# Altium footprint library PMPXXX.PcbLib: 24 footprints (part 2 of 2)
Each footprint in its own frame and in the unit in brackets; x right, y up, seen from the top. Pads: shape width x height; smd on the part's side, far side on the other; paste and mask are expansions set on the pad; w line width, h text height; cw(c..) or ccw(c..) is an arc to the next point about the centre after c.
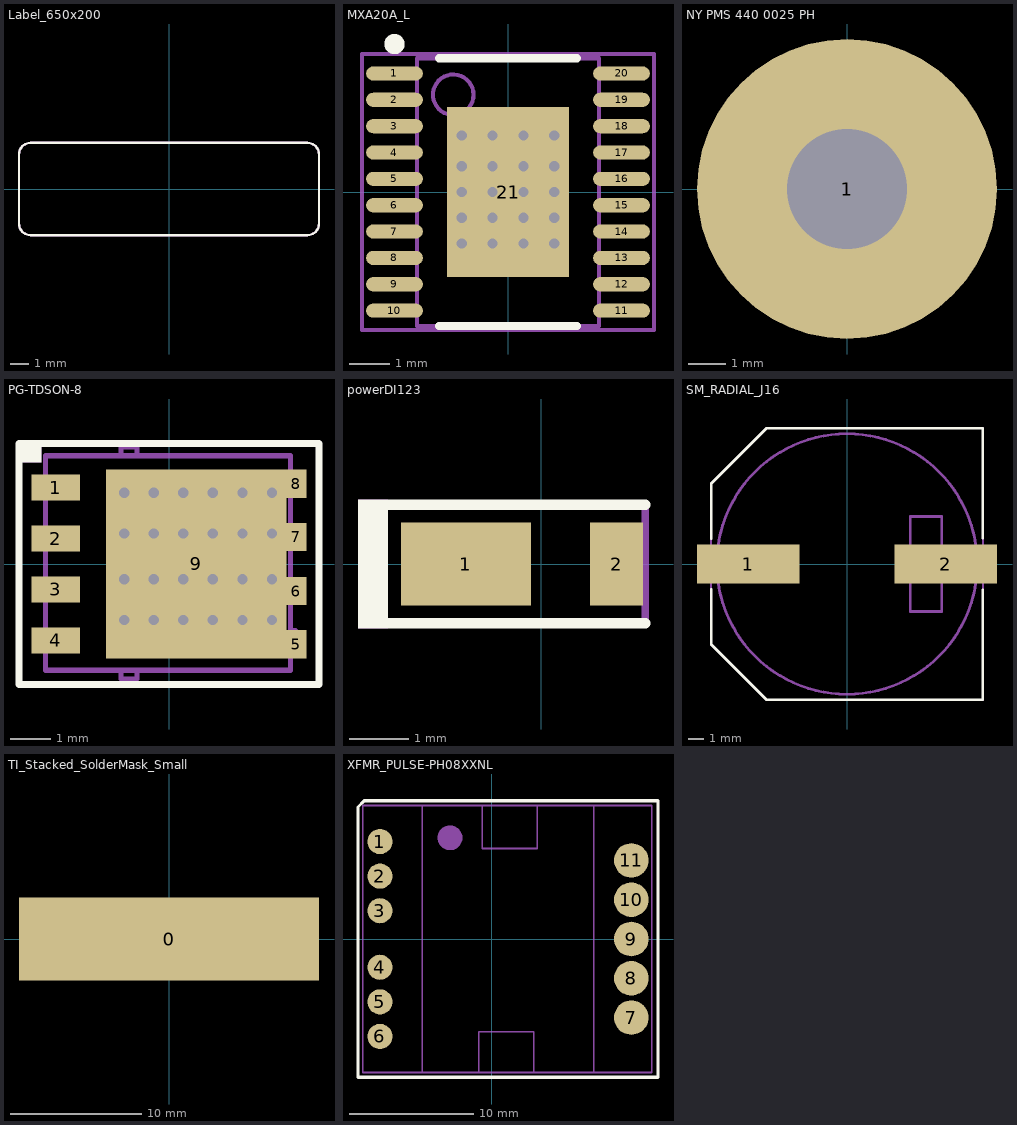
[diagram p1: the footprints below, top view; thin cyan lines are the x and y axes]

## Label_650x200 [mm] "Thermal Transfer Label"
height 0.025
Top Overlay:
  lines w0.127: -8.255,-1.905 ccw(c-7.62,-1.905) -7.62,-2.54 7.62,-2.54 ccw(c7.62,-1.905) 8.255,-1.905 8.255,1.905 ccw(c7.62,1.905) 7.62,2.54 -7.62,2.54 ccw(c-7.62,1.905) -8.255,1.905 -8.255,-1.905
Mechanical 5:
  lines w0.127: -8.255,-1.905 ccw(c-7.62,-1.905) -7.62,-2.54 7.62,-2.54 ccw(c7.62,-1.905) 8.255,-1.905 8.255,1.905 ccw(c7.62,1.905) 7.62,2.54 -7.62,2.54 ccw(c-7.62,1.905) -8.255,1.905 -8.255,-1.905
  text ".Designator" at -1.524,-0.508 h1.02
3D body: height 0.03, standoff 0, extent -8.268,-2.553 8.268,2.553

## MXA20A_L [mm] "TSOP, 20-Leads, Body 6.5x4.4mm, Pitch 0.65mm, Exposed Pad, IPC High Density"
height 1.1
pads (21):
  oval 1.4x0.35 smd: 1(-2.8,2.925) 2(-2.8,2.275) 3(-2.8,1.625) 4(-2.8,0.975) 5(-2.8,0.325) 6(-2.8,-0.325) 7(-2.8,-0.975) 8(-2.8,-1.625) 9(-2.8,-2.275) 10(-2.8,-2.925) 11(2.8,-2.925) 12(2.8,-2.275) 13(2.8,-1.625) 14(2.8,-0.975) 15(2.8,-0.325) 16(2.8,0.325) 17(2.8,0.975) 18(2.8,1.625) 19(2.8,2.275) 20(2.8,2.925)
  rect 3x4.2 smd: 21(0,0)
via 1.143,1.397 diameter 0.508 hole 0.254
via 0.381,1.397 diameter 0.508 hole 0.254
via -1.143,1.397 diameter 0.508 hole 0.254
via -0.381,1.397 diameter 0.508 hole 0.254
via -0.381,0.635 diameter 0.508 hole 0.254
via -1.143,0.635 diameter 0.508 hole 0.254
via 0.381,0.635 diameter 0.508 hole 0.254
via 1.143,0.635 diameter 0.508 hole 0.254
via -1.143,0 diameter 0.508 hole 0.254
via 0.381,0 diameter 0.508 hole 0.254
via 1.143,0 diameter 0.508 hole 0.254
via -0.381,-0.635 diameter 0.508 hole 0.254
via -1.143,-0.635 diameter 0.508 hole 0.254
via 0.381,-0.635 diameter 0.508 hole 0.254
via 1.143,-0.635 diameter 0.508 hole 0.254
via -0.381,-1.27 diameter 0.508 hole 0.254
via -1.143,-1.27 diameter 0.508 hole 0.254
via 0.381,-1.27 diameter 0.508 hole 0.254
via 1.143,-1.27 diameter 0.508 hole 0.254
via -0.381,0 diameter 0.508 hole 0.254
Top Overlay:
  circle w0.25: c-2.8,3.65 r0.125
  lines w0.2: -1.7,-3.3 1.7,-3.3 ; -1.7,3.3 1.7,3.3
Mechanical 5:
  circle w0.1: c-1.35,2.4 r0.5
  lines w0.1: -2.25,-3.3 2.25,-3.3 2.25,3.3 -2.25,3.3 -2.25,-3.3
  text ".Designator" at -1.524,-0.508 h1.02
Mechanical 15:
  lines w0.1: -0.5,0 0.5,0 ; 0,-0.5 0,0.5 ; -3.6,-3.4 3.6,-3.4 3.6,3.4 -3.6,3.4 -3.6,-3.4
3D body: height 1.1, standoff 0, extent -2.25,-3.3 2.25,3.3

## NY PMS 440 0025 PH [mm] "4-40 nylon screw and mounting hole"
height 1.905
pads (1):
  round 8 hole 3.2: 1(0,0)
Mechanical 5:
  circle w0.127: c0,0 r3.789
  text ".Designator" at -1.524,-0.508 h1.02
3D body: height 2.69, standoff -8.74, extent -3.302,-3.3 3.296,3.3

## PG-TDSON-8 [mm] "Infineon recommended land pattern"
height 1.1
pads (9):
  rect 1.2x0.65 smd: 1(-2.825,1.905) 2(-2.825,0.635) 3(-2.825,-0.635) 4(-2.825,-1.905)
  rect 0.5x0.7 smd: 5(3.175,-2) 6(3.175,-0.675) 7(3.175,0.675) 8(3.175,2)
  rect 4.5x4.7 smd paste-2.25: 9(0.675,0)
via 2.565,-1.397 diameter 0.508 hole 0.254
via 1.829,-1.397 diameter 0.508 hole 0.254
via 1.092,-1.397 diameter 0.508 hole 0.254
via 0.356,-1.397 diameter 0.508 hole 0.254
via -0.381,-1.397 diameter 0.508 hole 0.254
via -1.118,-1.397 diameter 0.508 hole 0.254
via -1.118,-0.381 diameter 0.508 hole 0.254
via -0.381,-0.381 diameter 0.508 hole 0.254
via 0.356,-0.381 diameter 0.508 hole 0.254
via 1.092,-0.381 diameter 0.508 hole 0.254
via 1.829,-0.381 diameter 0.508 hole 0.254
via 2.565,-0.381 diameter 0.508 hole 0.254
via 2.565,1.778 diameter 0.508 hole 0.254
via 1.829,1.778 diameter 0.508 hole 0.254
via 1.092,1.778 diameter 0.508 hole 0.254
via 0.356,1.778 diameter 0.508 hole 0.254
via -0.381,1.778 diameter 0.508 hole 0.254
via -1.118,1.778 diameter 0.508 hole 0.254
via -1.118,0.762 diameter 0.508 hole 0.254
via -0.381,0.762 diameter 0.508 hole 0.254
via 0.356,0.762 diameter 0.508 hole 0.254
via 1.092,0.762 diameter 0.508 hole 0.254
via 1.829,0.762 diameter 0.508 hole 0.254
via 2.565,0.762 diameter 0.508 hole 0.254
Top Overlay:
  rectangle: -3.74,2.528 -3.175,2.975
  lines w0.178: -3.74,-3 -3.74,0 -3.74,3 0.105,3 3.74,3 3.74,0 3.74,-3 -0.105,-3 -3.74,-3
Top Paste:
  rectangle: -1.475,0.95 -0.242,2.25
  rectangle: 0.058,0.95 1.291,2.25
  rectangle: 1.591,0.95 2.824,2.25
  rectangle: -1.475,-0.65 -0.242,0.65
  rectangle: 0.058,-0.65 1.291,0.65
  rectangle: 1.591,-0.65 2.824,0.65
  rectangle: 1.591,-2.25 2.824,-0.95
  rectangle: 0.058,-2.25 1.291,-0.95
  rectangle: -1.475,-2.25 -0.242,-0.95
Mechanical 5:
  rectangle: -3.74,2.528 -3.175,2.975
  lines w0.127: -3.075,-2.1 -3.2,-2.1 -3.2,-1.66 -3.075,-1.66 ; -3.075,-0.83 -3.2,-0.83 -3.2,-0.39 -3.075,-0.39 ; -3.075,0.44 -3.2,0.44 -3.2,0.88 -3.075,0.88 ; -3.075,1.71 -3.2,1.71 -3.2,2.15 -3.075,2.15 ; -1.2,-2.65 -1.2,-2.87 -0.8,-2.87 -0.8,-2.65 ; -1.2,2.7 -1.2,2.92 -0.8,2.92 -0.8,2.7 ; 3.025,-2.1 3.15,-2.1 3.15,-1.66 3.025,-1.66 ; 3.025,-0.83 3.15,-0.83 3.15,-0.39 3.025,-0.39 ; 3.025,0.44 3.15,0.44 3.15,0.88 3.025,0.88 ; 3.025,1.71 3.15,1.71 3.15,2.15 3.025,2.15 ; -3.075,-2.65 3.025,-2.65 3.025,2.7 -3.075,2.7 -3.075,-2.65
  text ".Designator" at -1.925,-0.5 h1.02
3D body: height 1.1, standoff 0, extent 1.778,-6.679 8.128,-0.889

## powerDI123 [mm] "Diodes Inc recommended land pattern, document number DS30628 Rev. 6-2"
height 1
pads (2):
  rect 2.2x1.4 smd: 1(-1.275,0)
  rect 0.9x1.4 smd: 2(1.275,0)
Top Overlay:
  rectangle: -3.099,-1.092 -2.591,1.092
  lines w0.178: -2.946,-1.003 1.759,-1.003 ; -2.946,1.003 1.759,1.003
Mechanical 5:
  rectangle: -3.099,-1.092 -2.591,1.092
  lines w0.127: -2.946,-1.003 1.759,-1.003 1.759,1.003 -2.946,1.003
  text ".Designator" at -2.35,-0.275 h0.76
3D body: height 1, standoff 0, extent -2.375,-0.965 1.525,0.965

## SM_RADIAL_J16 [mm] "16 x 16.5mm:  Panasonic J16"
height 17
pads (2):
  rect 6.5x2.5 smd: 1(-6.25,0) 2(6.25,0)
Top Overlay:
  lines w0.178: -8.6,-1.625 -8.6,-5.091 -5.091,-8.6 8.6,-8.6 8.6,-1.638 ; -8.6,1.625 -8.6,5.091 -5.091,8.6 8.6,8.6 8.6,1.638
Mechanical 5:
  lines w0.127: -8.6,-5.091 -5.091,-8.6 8.6,-8.6 8.6,-1.638 8.6,1.638 8.6,8.6 -5.091,8.6 -8.6,5.091 -8.6,1.625 -8.6,-1.625 -8.6,-5.091
  text ".Designator" at -1.524,-0.508 h1.02
Mechanical 13:
  circle w0.178: c0,0 r8.25
  lines w0.178: 4,-3 6,-3 6,3 4,3 4,-3
3D body: height 0.6, standoff 0, extent -8.601,-8.601 8.601,8.601
3D body: height 17, standoff 0.6, extent -8.259,-8.259 8.259,8.259
3D body: height 17, standoff 16.9, extent 4.001,-2.999 5.999,2.999

## TI_Stacked_SolderMask_Small [mm]
pads (1):
  rect 22.86x6.35 smd paste-3.175 mask-3.175: 0(0,0)
Top Solder:
  drawing of 18 lines, arcs and shapes, not listed

## XFMR_PULSE-PH08XXNL [mil] "Transformer, Pulse"
height 338.58
pads (11):
  round 80 smd: 1(-355,310) 2(-355,200) 3(-355,90) 4(-355,-90) 5(-355,-200) 6(-355,-310)
  round 110 smd: 7(445,-250) 8(445,-125) 9(445,0) 10(445,125) 11(445,250)
Top Overlay:
  lines w10: -425,-440 -425,420 -405,440 530,440 530,-440 -425,-440
Mechanical 5:
  circle w39.37: c-132,322 r19.68
  lines w5: -410,-425 -410,425 510,425 510,-425 -410,-425 ; -220,-425 -220,425 -30,425 -30,288 145,288 145,425 325,425 325,-425 135,-425 135,-295 -40,-295 -40,-425 -220,-425
  text ".Designator" at -114,-18 h40
Mechanical 13:
  circle w15.75: c-355,310 r15
  circle w20: c-355,200 r15.75
  circle w20: c-355,90 r15.75
  circle w20: c-355,-90 r15.75
  circle w20: c-355,-200 r15.75
  circle w20: c-355,-310 r15.75
  circle w20: c445,-250 r21.26
  circle w20: c445,-125 r21.26
  circle w20: c445,0 r21.26
  circle w20: c445,125 r21.26
  circle w20: c445,250 r21.26
3D body: height 339.37, standoff 330.71, extent -152.05,301.95 -111.95,342.05
3D body: height 196.85, standoff 0, extent 325,-420 505,420
3D body: height 196.85, standoff 0, extent -405,-420 -225,420
3D body: height 338.58, standoff 0, extent -225,-420 325,425
3D body: height 338.58, standoff 0, extent -39.98,-424.98 134.98,-295.02
3D body: height 236.22, standoff 0, extent 325.02,-424.98 509.98,424.98
3D body: height 338.58, standoff 0, extent -219.98,-424.98 324.98,424.98
3D body: height 236.22, standoff 0, extent -409.98,-424.98 -220.02,424.98
3D body: height 275.59, standoff 0, extent 429.73,-265.27 460.27,-234.73
3D body: height 275.59, standoff 0, extent 429.73,-140.27 460.27,-109.73
3D body: height 275.59, standoff 0, extent -370.27,-325.27 -339.73,-294.73
3D body: height 275.59, standoff 0, extent -370.27,294.73 -339.73,325.27
3D body: height 275.59, standoff 0, extent -370.27,184.73 -339.73,215.27
3D body: height 275.59, standoff 0, extent -370.27,74.73 -339.73,105.27
3D body: height 275.59, standoff 0, extent 429.73,234.73 460.27,265.27
3D body: height 275.59, standoff 0, extent 429.73,109.73 460.27,140.27
3D body: height 275.59, standoff 0, extent 429.73,-15.27 460.27,15.27
3D body: height 275.59, standoff 0, extent -370.27,-105.27 -339.73,-74.73
3D body: height 275.59, standoff 0, extent -370.27,-215.27 -339.73,-184.73
3D body: height 338.58, standoff 0, extent -29.98,288.02 144.98,424.98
